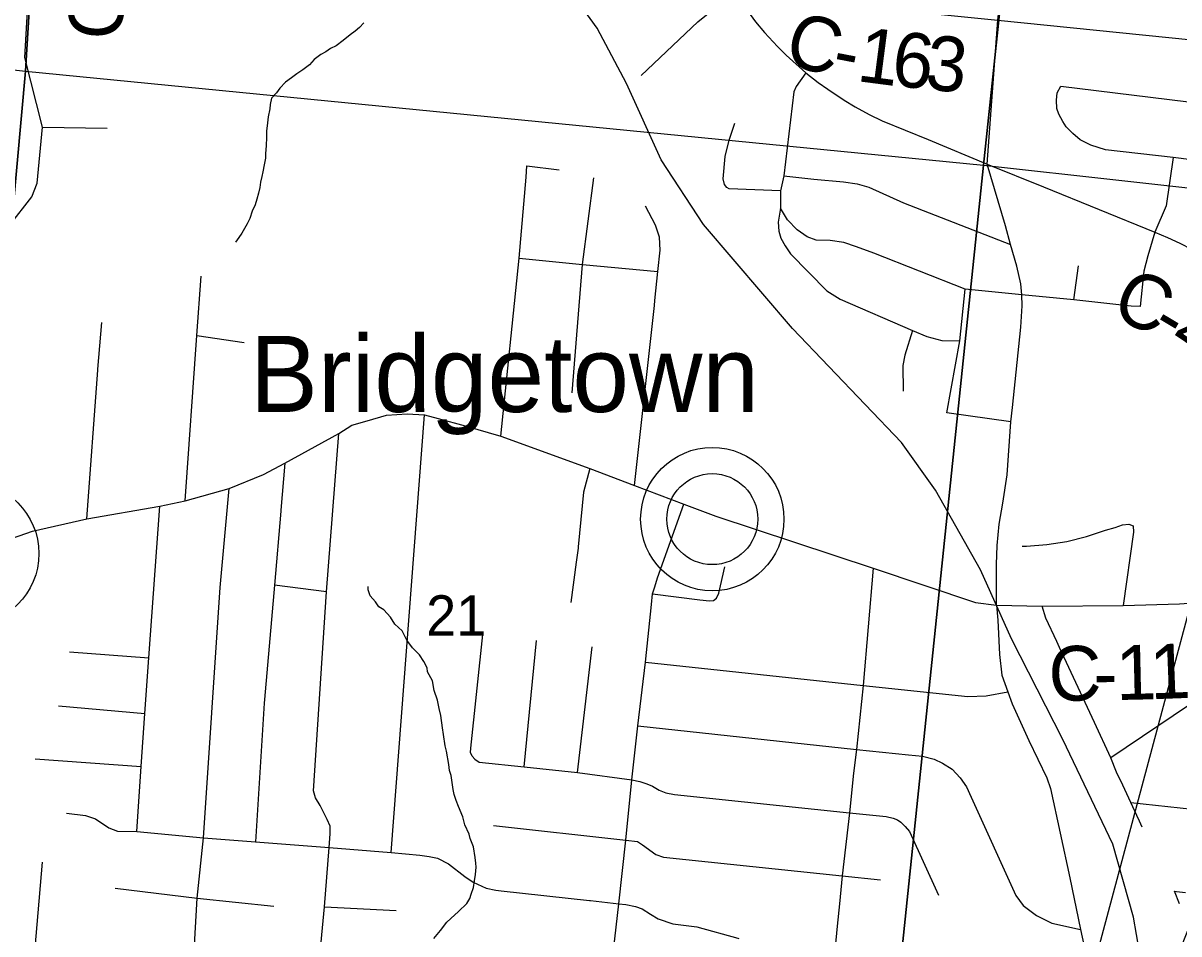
# Model space of a CAD drawing. Extents: x 0 to 43.4, y -8.1 to 22.
# Drawn here: x 6.05 to 7.249, y 19.598 to 20.543 of the extents above; entities that cross this region are included whole.
import ezdxf

# ---------------------------------------------------------------- set-up
doc = ezdxf.new("R2010")
doc.units = 0
for name, color, linetype in [('GM_X_Corporation', 7, 'Continuous'), ('GM_X_County_Road', 7, 'Continuous'), ('GM_X_County_Road_Text', 7, 'Continuous'), ('GM_X_Minor_River', 7, 'Continuous'), ('GM_X_Rail_Line', 7, 'Continuous'), ('GM_X_Section_Text', 7, 'Continuous'), ('GM_X_State_Route', 7, 'Continuous'), ('GM_X_Township_Road', 7, 'Continuous'), ('GM_X_Unincorporated', 7, 'Continuous'), ('GM_X_Unincorporated_Location', 7, 'Continuous'), ('GM_X_Unincorporated_Text', 7, 'Continuous'), ('SH_Text', 7, 'Continuous')]:
    doc.layers.add(name, color=color, linetype=linetype)

msp = doc.modelspace()

# ---------------------------------------------------------------- linework, layer by layer
at = {"layer": 'GM_X_Corporation'}
for points in [[(6.077, 20.9), (5.0731, 20.9), (5.0456, 20.604), (6.0521, 20.4929)], [(7.0997, 20.9), (6.077, 20.9), (6.0521, 20.4929), (7.0465, 20.3953)], [(8.1157, 20.9), (7.0997, 20.9), (7.0465, 20.3953), (8.0517, 20.2839)], [(6.0521, 20.4929), (5.9616, 19.4927), (4.9462, 19.5972), (5.0456, 20.604)], [(7.0465, 20.3953), (6.9413, 19.3833), (5.9616, 19.4927), (6.0521, 20.4929)], [(7.0465, 20.3953), (8.0517, 20.2839), (7.955, 19.3167), (7.3077, 19.3879), (7.3067, 19.3445), (6.9413, 19.3833)]]:
    msp.add_lwpolyline(points, close=True, dxfattribs=at)
msp.add_lwpolyline([(7.2501, 19.6288), (7.2448, 19.6419), (7.2468, 19.6417), (7.2562, 19.6406)], dxfattribs=at)
at = {"layer": 'GM_X_County_Road'}
for points in [[(6.0357, 20.3327), (6.0589, 20.3624), (6.0642, 20.3767), (6.0699, 20.4347), (6.0514, 20.507), (6.0739, 20.9)], [(6.5797, 20.9), (6.5922, 20.8807), (6.609, 20.8554), (6.6257, 20.828), (6.6385, 20.8086), (6.6511, 20.7886), (6.6599, 20.7739), (6.6778, 20.7442), (6.7353, 20.6548), (6.7877, 20.5749), (6.8101, 20.5442), (6.8193, 20.533), (6.8328, 20.5185), (6.8419, 20.5096), (6.8623, 20.4912), (6.8749, 20.4813), (6.8851, 20.4742), (6.902, 20.4628), (6.9135, 20.4559), (6.9278, 20.4481), (6.9415, 20.4415), (6.989, 20.4219), (7.0504, 20.3964)], [(6.7877, 20.5749), (6.803, 20.5834), (6.8139, 20.5861), (6.8329, 20.5848), (6.857, 20.5785), (6.8813, 20.5697), (6.9073, 20.5639), (6.9367, 20.5584), (7.0614, 20.5459), (7.5701, 20.4942), (7.7383, 20.4795), (7.8165, 20.4727), (7.8632, 20.4681), (7.8783, 20.4665)], [(7.0504, 20.3964), (7.0614, 20.5459), (7.0645, 20.575)], [(7.0602, 19.9389), (7.0602, 19.9628), (7.0602, 19.9809), (7.0609, 20.0006), (7.0628, 20.0227), (7.0668, 20.0446), (7.0713, 20.0741), (7.075, 20.129), (7.0767, 20.1441), (7.0855, 20.2273), (7.0867, 20.2494), (7.0864, 20.2608), (7.0855, 20.2723), (7.0811, 20.2905), (7.0747, 20.3132), (7.0694, 20.3324), (7.0504, 20.3964)], [(7.0504, 20.3964), (7.1089, 20.373), (7.2246, 20.326), (7.2376, 20.3205), (7.2504, 20.3143), (7.2625, 20.3083), (7.2765, 20.3), (7.2892, 20.2926), (7.3046, 20.2821), (7.3658, 20.239), (7.373, 20.2341), (7.4302, 20.1936), (7.4372, 20.1889), (7.4624, 20.1709), (7.5271, 20.125)], [(7.0602, 19.9389), (7.1074, 19.9376), (7.1917, 19.9385), (7.2501, 19.9402), (7.3184, 19.945), (7.3355, 19.9457), (7.384, 19.9485), (7.4255, 19.9523), (7.4747, 19.9545)]]:
    msp.add_lwpolyline(points, dxfattribs=at)
at = {"layer": 'GM_X_Minor_River'}
for points in [[(6.4033, 20.5432), (6.3989, 20.5381), (6.3943, 20.5344), (6.3892, 20.5308), (6.3818, 20.5246), (6.3747, 20.5191), (6.3689, 20.5163), (6.3639, 20.513), (6.3589, 20.5102), (6.3519, 20.5051), (6.3471, 20.4996), (6.3401, 20.4945), (6.3339, 20.4901), (6.3284, 20.4861), (6.3222, 20.4814), (6.3163, 20.4752), (6.3127, 20.4703), (6.3076, 20.4648), (6.3062, 20.4584), (6.3057, 20.4539), (6.3042, 20.4456), (6.3033, 20.4395), (6.3022, 20.4308), (6.3024, 20.4243), (6.3021, 20.4156), (6.3014, 20.4076), (6.3012, 20.4027), (6.2999, 20.3959), (6.2985, 20.3884), (6.2976, 20.3838), (6.2962, 20.3778), (6.2953, 20.3721), (6.2939, 20.3665), (6.2922, 20.3601), (6.2905, 20.3544), (6.2876, 20.3477), (6.285, 20.3402), (6.2822, 20.3346), (6.2769, 20.3249), (6.2737, 20.3204), (6.2701, 20.3156)], [(6.4917, 19.7735), (6.4892, 19.7873), (6.4879, 19.7927), (6.486, 19.8045), (6.4851, 19.8114), (6.4833, 19.8244), (6.4816, 19.8317), (6.48, 19.8401), (6.4765, 19.8501), (6.4746, 19.8604), (6.4696, 19.8697), (6.469, 19.8739), (6.4655, 19.8805), (6.4611, 19.8871), (6.4538, 19.8946), (6.448, 19.9024), (6.443, 19.9121), (6.4357, 19.9192), (6.431, 19.9265), (6.424, 19.934), (6.4188, 19.9372), (6.4156, 19.9423), (6.4101, 19.9486), (6.408, 19.9547), (6.4078, 19.9582)], [(6.476, 19.5928), (6.4831, 19.6013), (6.4895, 19.6098), (6.4938, 19.6138), (6.5017, 19.6208), (6.5103, 19.6292), (6.5135, 19.6344), (6.5148, 19.639), (6.5173, 19.6457), (6.5183, 19.6529), (6.5193, 19.6593), (6.52, 19.6669), (6.5197, 19.6711), (6.5188, 19.6768), (6.5173, 19.6879), (6.5138, 19.6968), (6.5128, 19.701), (6.5082, 19.711), (6.5062, 19.7191), (6.5016, 19.7299), (6.4992, 19.736), (6.4971, 19.7422), (6.4962, 19.7475), (6.494, 19.7621), (6.4923, 19.7674), (6.4917, 19.7735)]]:
    msp.add_lwpolyline(points, dxfattribs=at)
at = {"layer": 'GM_X_Rail_Line'}
msp.add_lwpolyline([(7.2632, 18.7074), (7.2074, 18.8505), (7.1644, 18.9863), (7.1583, 19.0746), (7.1652, 19.1715), (7.1865, 19.2573), (7.219, 19.4133), (7.2179, 19.5252), (7.2022, 19.6149), (7.1807, 19.6909), (7.1291, 19.7994), (7.0756, 19.9038), (7.0435, 19.9755), (6.9966, 20.0582), (6.9615, 20.1077), (6.8485, 20.2259), (6.7559, 20.3339), (6.7119, 20.4011), (6.6759, 20.48), (6.6457, 20.5375), (6.5931, 20.6104)], dxfattribs=at)
at = {"layer": 'GM_X_State_Route'}
for points in [[(6.0309, 20.0057), (6.0594, 20.0157), (6.1157, 20.0285), (6.1915, 20.0417), (6.2178, 20.0472), (6.2635, 20.0599), (6.2994, 20.0745), (6.3215, 20.0863), (6.3775, 20.117), (6.3909, 20.1255), (6.4069, 20.1301), (6.4268, 20.1359), (6.4482, 20.1373), (6.4662, 20.1364), (6.4805, 20.1326), (6.5086, 20.125), (6.5455, 20.1141), (6.6379, 20.0806), (6.6843, 20.0631), (6.7356, 20.0436), (6.7689, 20.031), (6.932, 19.9773), (7.0383, 19.9416), (7.0602, 19.9389)], [(7.0602, 19.9389), (7.0616, 19.9231), (7.0631, 19.8875), (7.0657, 19.8662), (7.0718, 19.849), (7.0763, 19.8363), (7.0936, 19.7983), (7.1124, 19.7595), (7.1163, 19.7484), (7.1361, 19.6557), (7.1474, 19.6024), (7.1549, 19.5672), (7.1606, 19.5374), (7.1591, 19.4991), (7.1588, 19.4911), (7.158, 19.4508)]]:
    msp.add_lwpolyline(points, dxfattribs=at)
at = {"layer": 'GM_X_Township_Road'}
for p, q in [((7.127, 20.4775), (7.3158, 20.454)), ((6.0699, 20.4347), (6.137, 20.4337)), ((7.1403, 20.2557), (7.1451, 20.2911)), ((6.1272, 20.1836), (6.1314, 20.2322)), ((6.2302, 20.2188), (6.2793, 20.2115)), ((6.4319, 19.682), (6.4662, 20.1364)), ((7.075, 20.129), (7.0087, 20.1383)), ((6.3215, 20.0863), (6.3173, 20.0374)), ((6.3648, 19.9527), (6.3106, 19.9596)), ((6.5699, 19.7709), (6.5827, 19.9022)), ((6.6253, 19.7652), (6.6405, 19.8954)), ((6.0977, 19.8903), (6.1803, 19.8841)), ((7.3093, 19.8684), (7.1786, 19.7804)), ((6.0864, 19.8343), (6.1762, 19.8263)), ((6.0621, 19.7793), (6.1723, 19.7713)), ((7.1995, 19.7339), (7.2842, 19.725)), ((7.2114, 19.7085), (7.2085, 19.7145)), ((6.3625, 19.6258), (6.437, 19.6221))]:
    msp.add_line(p, q, dxfattribs=at)
for points in [[(6.6912, 20.4884), (6.7499, 20.5442), (6.7877, 20.5749)], [(6.8623, 20.4912), (6.8522, 20.4769), (6.8497, 20.4715), (6.8392, 20.3845), (6.8358, 20.3689), (6.8358, 20.3508), (6.8336, 20.3362), (6.8341, 20.3269), (6.8363, 20.3196), (6.8408, 20.3117), (6.8461, 20.3033), (6.8839, 20.2649), (6.8978, 20.2564), (6.9728, 20.2237), (6.9879, 20.2177), (7.0033, 20.2136), (7.022, 20.213)], [(7.1249, 20.4484), (7.1227, 20.4542), (7.1225, 20.4628), (7.1232, 20.4706), (7.127, 20.4775)], [(7.5565, 20.368), (7.4581, 20.3753), (7.4464, 20.3769), (7.385, 20.3852), (7.2433, 20.4035), (7.1732, 20.4114), (7.1581, 20.4162), (7.1468, 20.4218), (7.1393, 20.4283), (7.1324, 20.4352), (7.1288, 20.4407), (7.1249, 20.4484)], [(6.8358, 20.3689), (6.7827, 20.3708), (6.7801, 20.3721), (6.7779, 20.3755), (6.7762, 20.3813), (6.7785, 20.4044), (6.7825, 20.4214), (6.7884, 20.439)], [(6.5719, 20.3829), (6.5727, 20.3948), (6.6061, 20.3906)], [(7.2433, 20.4035), (7.2362, 20.3531), (7.2246, 20.326), (7.217, 20.3013), (7.213, 20.2854), (7.2091, 20.2486), (7.1999, 20.2492), (7.1871, 20.2504), (7.1403, 20.2557), (7.0864, 20.2608), (7.0275, 20.2667), (6.9327, 20.3042), (6.9148, 20.3108), (6.9017, 20.315), (6.8873, 20.3172), (6.873, 20.3177), (6.8635, 20.3211), (6.8533, 20.3283), (6.8433, 20.3386), (6.8358, 20.3508)], [(6.5455, 20.1141), (6.5647, 20.299), (6.5719, 20.3829)], [(6.8392, 20.3845), (6.8704, 20.3809), (6.9011, 20.3782), (6.9154, 20.3761), (6.9274, 20.3727), (6.9637, 20.3564), (7.0747, 20.3132)], [(6.6196, 20.1592), (6.6304, 20.2922), (6.6421, 20.3822)], [(6.7056, 20.2548), (6.7087, 20.2849), (6.7108, 20.3073), (6.7103, 20.3208), (6.7063, 20.3333), (6.6959, 20.3527)], [(6.5647, 20.299), (6.6304, 20.2922), (6.7087, 20.2849)], [(6.2178, 20.0472), (6.2302, 20.2188), (6.2346, 20.2802)], [(7.0087, 20.1383), (7.022, 20.213), (7.0275, 20.2667)], [(6.6843, 20.0631), (6.705, 20.2498), (6.7056, 20.2548)], [(6.9728, 20.2237), (6.9648, 20.1983), (6.9627, 20.1874), (6.9631, 20.161)], [(6.1157, 20.0285), (6.1272, 20.1827), (6.1272, 20.1836)], [(6.3486, 19.4465), (6.3519, 19.5047), (6.3566, 19.564), (6.3625, 19.6258), (6.3673, 19.6875), (6.3684, 19.7015), (6.3686, 19.7094), (6.3654, 19.7163), (6.3579, 19.731), (6.3531, 19.7389), (6.3512, 19.7462), (6.3648, 19.9527), (6.3775, 20.117)], [(6.6379, 20.0806), (6.6315, 20.056), (6.626, 19.9994), (6.6258, 19.998)], [(6.2368, 19.6973), (6.2543, 19.957), (6.2635, 20.0599)], [(6.1677, 19.704), (6.1723, 19.7713), (6.1762, 19.8263), (6.1803, 19.8841), (6.1915, 20.0417)], [(6.3173, 20.0374), (6.3172, 20.0365), (6.3106, 19.9596), (6.3004, 19.841)], [(6.6587, 19.5473), (6.6682, 19.629), (6.6754, 19.695), (6.6814, 19.7575), (6.6878, 19.8136), (6.6956, 19.8795), (6.7019, 19.9395), (6.7031, 19.9505), (6.7056, 19.958), (6.7081, 19.9673), (6.7356, 20.0436)], [(7.0866, 20.0002), (7.0911, 20.0001), (7.1122, 20.0016), (7.1332, 20.0049), (7.1534, 20.0099), (7.1731, 20.0168), (7.1833, 20.0194), (7.1909, 20.0222), (7.1974, 20.023), (7.2021, 20.0211), (7.2024, 20.0144), (7.1917, 19.9385)], [(6.6258, 19.998), (6.6239, 19.9835), (6.6184, 19.9416)], [(6.7031, 19.9505), (6.752, 19.9443), (6.7622, 19.9433), (6.7664, 19.9437), (6.7695, 19.9462), (6.7719, 19.9512), (6.7782, 19.9786)], [(6.932, 19.9773), (6.9217, 19.8553), (6.9148, 19.7889)], [(7.1256, 19.895), (7.1227, 19.9012), (7.1114, 19.9252), (7.1074, 19.9376)], [(6.5159, 19.7822), (6.5142, 19.786), (6.5145, 19.7903), (6.5269, 19.9082)], [(7.1912, 19.7519), (7.1848, 19.7656), (7.1786, 19.7804), (7.1618, 19.8169), (7.1256, 19.895)], [(6.6956, 19.8795), (6.9217, 19.8553), (7.0303, 19.8439), (7.0492, 19.8448), (7.0718, 19.849)], [(6.3004, 19.841), (6.3001, 19.8371), (6.291, 19.6931)], [(6.6878, 19.8136), (6.9148, 19.7889), (6.9687, 19.7835), (6.9833, 19.782), (6.9954, 19.7791), (7.004, 19.7747), (7.0139, 19.7686), (7.0223, 19.7595), (7.0291, 19.7502), (7.0338, 19.7397), (7.0802, 19.6376), (7.0877, 19.6273), (7.1017, 19.6166), (7.1174, 19.6087), (7.1474, 19.6024)], [(6.9148, 19.7889), (6.9117, 19.7645), (6.9075, 19.7233), (6.8999, 19.6579), (6.897, 19.6288)], [(6.5159, 19.7822), (6.5186, 19.779), (6.523, 19.776), (6.5699, 19.7709), (6.6253, 19.7652), (6.6814, 19.7575), (6.6897, 19.7557), (6.6972, 19.7533), (6.7031, 19.7509), (6.71, 19.747), (6.717, 19.744), (6.7258, 19.7422), (6.9075, 19.7233), (6.9456, 19.7196), (6.9529, 19.7178), (6.9573, 19.7161), (6.9609, 19.7136), (6.9654, 19.7092), (6.9697, 19.7039), (6.9998, 19.6379)], [(7.2085, 19.7145), (7.2057, 19.7206), (7.1995, 19.7339), (7.1912, 19.7519)], [(6.0946, 19.7228), (6.1146, 19.7205), (6.1249, 19.7172), (6.1387, 19.7077), (6.1477, 19.7042), (6.1677, 19.704), (6.2368, 19.6973), (6.291, 19.6931), (6.3673, 19.6875), (6.4319, 19.682), (6.4614, 19.6795), (6.4713, 19.678), (6.48, 19.6762), (6.4913, 19.6703), (6.5081, 19.6573), (6.5169, 19.6515), (6.5302, 19.645), (6.5405, 19.6432)], [(6.5379, 19.7102), (6.6754, 19.695), (6.6874, 19.6937), (6.6928, 19.6901), (6.7064, 19.68), (6.7145, 19.6772), (6.7608, 19.6723)], [(6.2277, 19.5861), (6.2305, 19.6346), (6.2368, 19.6973)], [(6.1638, 19.3976), (6.0692, 19.4069), (6.064, 19.4097), (6.0591, 19.4133), (6.0548, 19.4192), (6.0513, 19.428), (6.0501, 19.4398), (6.0534, 19.478), (6.0699, 19.672)], [(6.7608, 19.6723), (6.8999, 19.6579), (6.9398, 19.6539)], [(6.1454, 19.6453), (6.2305, 19.6346), (6.3101, 19.6266)], [(6.5405, 19.6432), (6.5461, 19.6423), (6.6376, 19.6324), (6.6386, 19.6323)], [(6.6386, 19.6323), (6.6682, 19.629), (6.6753, 19.6283), (6.6852, 19.6262), (6.6923, 19.6236), (6.7011, 19.6183), (6.7089, 19.6134), (6.7241, 19.6081), (6.7491, 19.605), (6.7915, 19.5931), (6.7925, 19.593)], [(6.897, 19.6288), (6.8948, 19.6056), (6.8924, 19.5804), (6.887, 19.5194), (6.8793, 19.4597), (6.8713, 19.3847)]]:
    msp.add_lwpolyline(points, dxfattribs=at)
at = {"layer": 'GM_X_Unincorporated'}
for centre, radius in [((6.7651, 20.0281), 0.0744), ((6.7651, 20.0281), 0.0472), ((5.9917, 19.9923), 0.0744)]:
    msp.add_circle(centre, radius, dxfattribs=at)
at = {"layer": 'GM_X_Unincorporated_Location'}
msp.add_line((6.7651, 20.0281), (6.7651, 20.0281), dxfattribs=at)
at = {"layer": 'SH_Text'}
msp.add_lwpolyline([(7.4161, 19.9964), (6.9921, 18.9339), (7.4161, 20.5159)], close=True, dxfattribs=at)

# ---------------------------------------------------------------- texts
at = {"layer": 'GM_X_County_Road_Text'}
for s, height, rotation, p in [('C-161', 0.05682, 86.6984, (6.1521, 20.5245)), ('C', 0.0568, 343.9721, (6.8375, 20.5018)), ('1', 0.0568, 352.608, (6.9139, 20.4828)), ('6', 0.0568, 353.9378, (6.9498, 20.4782)), ('3', 0.0568, 354.1548, (6.9846, 20.4745)), ('-', 0.0568, 349.1438, (6.8875, 20.4877)), ('C', 0.0568, 334.8407, (7.1768, 20.2399)), ('-', 0.0568, 329.2287, (7.2174, 20.2209)), ('4', 0.0568, 325.9216, (7.2366, 20.2095)), ('C', 0.0568, 0.6766, (7.1144, 19.8394)), ('1', 0.0568, 1.2816, (7.1845, 19.8403)), ('1', 0.0568, 2.1479, (7.2201, 19.8411)), ('-', 0.0568, 0.8269, (7.1609, 19.84))]:
    msp.add_text(s, height=height, rotation=rotation, dxfattribs=at).set_placement(p)
at = {"layer": 'GM_X_Section_Text'}
msp.add_text('21', height=0.04186, rotation=0, dxfattribs=at).set_placement((6.4681, 19.9072))
at = {"layer": 'GM_X_Unincorporated_Text'}
msp.add_text('Bridgetown', height=0.07898, rotation=0, dxfattribs=at).set_placement((6.2852, 20.1393))

doc.saveas('drawing.dxf')
